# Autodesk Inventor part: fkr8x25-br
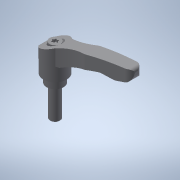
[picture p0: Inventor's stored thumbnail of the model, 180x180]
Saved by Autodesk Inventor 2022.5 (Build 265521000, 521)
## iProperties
Created: 2017-09
Part Number: fkr8x25-br
Material: 一般
Document SubType Name: Modeling
Designer: imaocorp
Density: 1 g/cm^3
Appearance: 既定
Author: imaocorp
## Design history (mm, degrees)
node "fkr8x25-br.x_t1"
node "fkr8x25-br"
node "Base1"
